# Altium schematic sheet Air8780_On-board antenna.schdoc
size 307 x 218 mm; Symbol: Drawing-Symbol_A4; Device: Drawing-Symbol_A4; Company: 嘉立创EDA; Version: V1.0; Page Size: A4; @Project Name: New Project_2026-06-16_15-44-20; @Page Count: 1; @Update Date: 2026-06-16; @Create Date: 2026-06-16; @Schematic Name: Schematic1; @Page No: 1; @Page Name: P1; @Board Name: Board1; @Create Time: 07:44:23; @Update Time: 15:44:23; Title Block Position: 3; Size: A4; Width: 1170; Height: 825; Region Start: 1; X Region Count: 6; Y Region Count: 4; Blade Width: 10
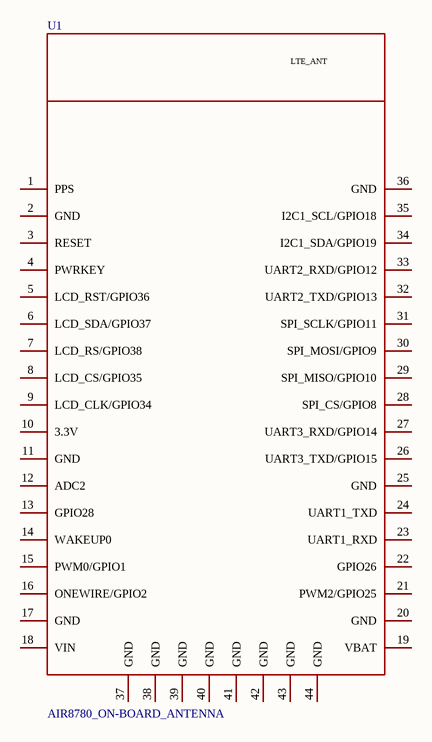
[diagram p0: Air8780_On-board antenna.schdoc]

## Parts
U1  AIR8780_ON-BOARD_ANTENNA  [AIR8780_ON-BOARD_ANTENNA]

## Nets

Not connected (* = marked no-connect by the designer): U1 1(PPS) 2(GND) 3(RESET) 4(PWRKEY) 5(LCD_RST/GPIO36) 6(LCD_SDA/GPIO37) 7(LCD_RS/GPIO38) 8(LCD_CS/GPIO35) 9(LCD_CLK/GPIO34) 10(3.3V) 11(GND) 12(ADC2) 13(GPIO28) 14(WAKEUP0) 15(PWM0/GPIO1) 16(ONEWIRE/GPIO2) 17(GND) 18(VIN) 19(VBAT) 20(GND) 21(PWM2/GPIO25) 22(GPIO26) 23(UART1_RXD) 24(UART1_TXD) 25(GND) 26(UART3_TXD/GPIO15) 27(UART3_RXD/GPIO14) 28(SPI_CS/GPIO8) 29(SPI_MISO/GPIO10) 30(SPI_MOSI/GPIO9) 31(SPI_SCLK/GPIO11) 32(UART2_TXD/GPIO13) 33(UART2_RXD/GPIO12) 34(I2C1_SDA/GPIO19) 35(I2C1_SCL/GPIO18) 36(GND) 37(GND) 38(GND) 39(GND) 40(GND) 41(GND) 42(GND) 43(GND) 44(GND)

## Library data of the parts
U1 = AIR8780_ON-BOARD_ANTENNA: Add into BOM: yes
